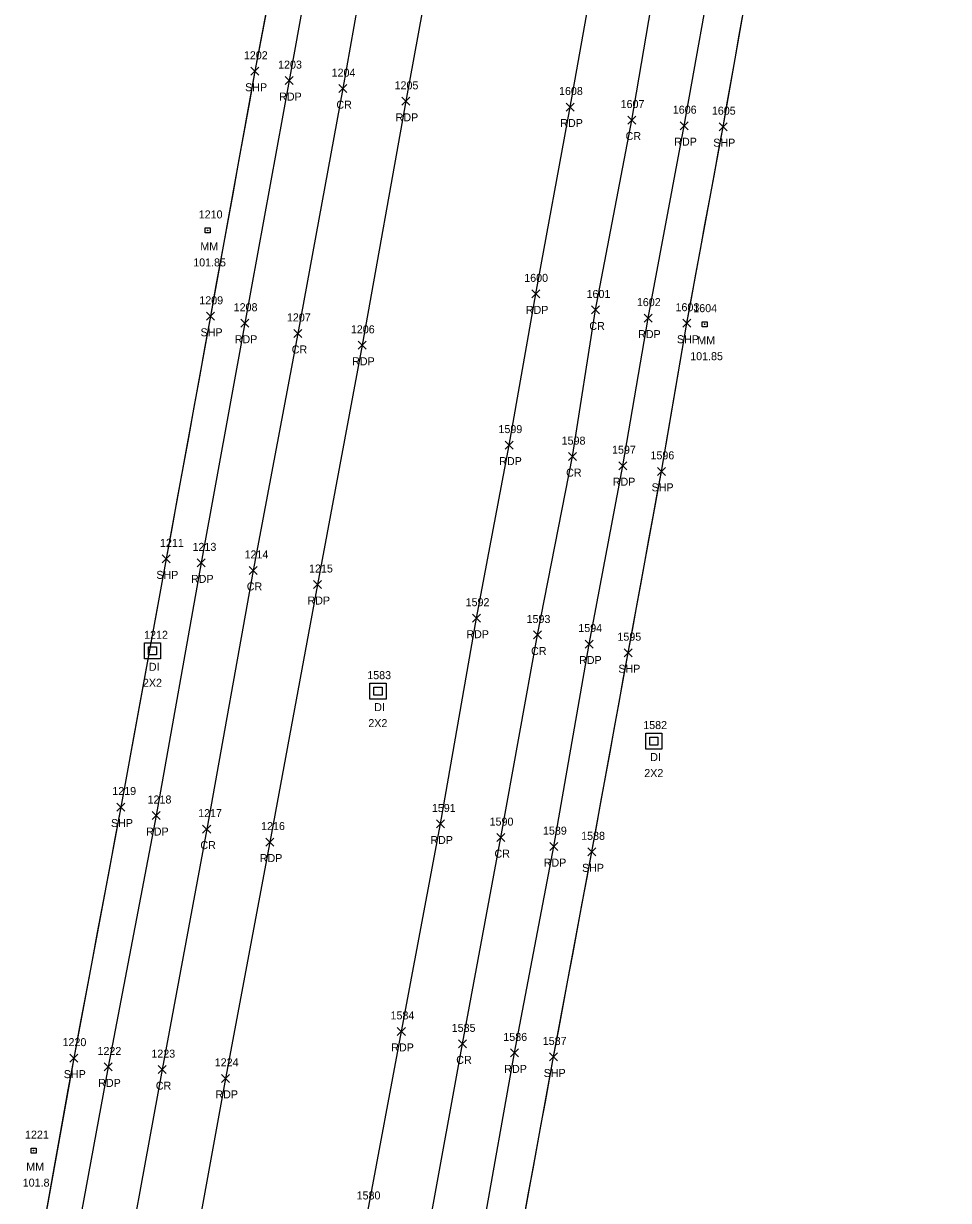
# Model space of a CAD drawing. Extents: x 1472022 to 1479249, y 777216 to 786527.
# Drawn here: x 1473773 to 1474004.1, y 780581.9 to 780876.1 of the extents above; entities that cross this region are included whole.
import ezdxf

# ---------------------------------------------------------------- set-up
doc = ezdxf.new("R2010")
doc.units = 0
for name, color, linetype in [('D_A', 7, 'Continuous'), ('D_C', 7, 'Continuous'), ('D_I', 7, 'Continuous'), ('DS', 7, 'Continuous'), ('LSOGP', 7, 'Continuous'), ('P_A', 7, 'Continuous'), ('P_I', 7, 'Continuous'), ('P_TIC', 7, 'Continuous'), ('PET', 7, 'Continuous'), ('PRC', 7, 'Continuous'), ('PSP', 7, 'Continuous'), ('S_A', 7, 'Continuous'), ('S_C', 7, 'Continuous'), ('S_I', 7, 'Continuous'), ('SRM', 7, 'Continuous')]:
    doc.layers.add(name, color=color, linetype=linetype)

msp = doc.modelspace()

# ---------------------------------------------------------------- linework, layer by layer
at = {"layer": 'DS'}
for p, q in [((1473803.21, 780721.26), (1473807.21, 780721.26)), ((1473803.21, 780717.26), (1473803.21, 780721.26)), ((1473807.21, 780721.26), (1473807.21, 780717.26)), ((1473804.21, 780718.26), (1473804.21, 780720.26)), ((1473804.21, 780720.26), (1473806.21, 780720.26)), ((1473806.21, 780718.26), (1473804.21, 780718.26)), ((1473805.22, 780719.27), (1473805.22, 780719.27)), ((1473805.22, 780719.27), (1473805.22, 780719.27)), ((1473806.21, 780720.26), (1473806.21, 780718.26)), ((1473807.21, 780717.26), (1473803.21, 780717.26)), ((1473859.53, 780711.19), (1473863.53, 780711.19)), ((1473859.53, 780707.19), (1473859.53, 780711.19)), ((1473860.53, 780708.19), (1473860.53, 780710.19)), ((1473860.53, 780710.19), (1473862.53, 780710.19)), ((1473862.53, 780710.19), (1473862.53, 780708.19)), ((1473863.53, 780711.19), (1473863.53, 780707.19)), ((1473863.53, 780707.19), (1473859.53, 780707.19)), ((1473862.53, 780708.19), (1473860.53, 780708.19)), ((1473861.54, 780709.19), (1473861.54, 780709.19)), ((1473861.54, 780709.19), (1473861.54, 780709.19)), ((1473928.48, 780698.71), (1473932.48, 780698.71)), ((1473928.48, 780694.71), (1473928.48, 780698.71)), ((1473929.48, 780695.71), (1473929.48, 780697.71)), ((1473929.48, 780697.71), (1473931.48, 780697.71)), ((1473931.48, 780697.71), (1473931.48, 780695.71)), ((1473932.48, 780698.71), (1473932.48, 780694.71)), ((1473932.48, 780694.71), (1473928.48, 780694.71)), ((1473931.48, 780695.71), (1473929.48, 780695.71)), ((1473930.49, 780696.71), (1473930.49, 780696.71)), ((1473930.49, 780696.71), (1473930.49, 780696.71))]:
    msp.add_line(p, q, dxfattribs=at)
at = {"layer": 'LSOGP'}
for points in [[(1473833.75, 780879.79), (1473832.27, 780871.97), (1473830.79, 780864.16), (1473829.4, 780856.5), (1473828.01, 780848.84), (1473826.62, 780841.19), (1473825.22, 780833.53), (1473823.83, 780825.87), (1473822.44, 780818.21), (1473821.05, 780810.56), (1473819.66, 780802.9), (1473818.28, 780795.32), (1473816.9, 780787.74), (1473815.52, 780780.16), (1473814.14, 780772.58), (1473812.76, 780765), (1473811.38, 780757.42), (1473810, 780749.84), (1473808.62, 780742.26), (1473807.2, 780734.51), (1473805.78, 780726.75), (1473804.36, 780718.99), (1473802.95, 780711.24), (1473801.53, 780703.48), (1473800.11, 780695.73), (1473798.69, 780687.97), (1473797.28, 780680.22), (1473795.8, 780672.37), (1473794.33, 780664.52), (1473792.86, 780656.68), (1473791.38, 780648.83), (1473789.91, 780640.99), (1473788.44, 780633.14), (1473786.96, 780625.29), (1473785.49, 780617.45), (1473784.06, 780609.5), (1473782.64, 780601.56), (1473781.22, 780593.62), (1473779.79, 780585.68), (1473778.37, 780577.73)], [(1473898.23, 780578.62), (1473899.25, 780584.21), (1473900.28, 780589.8), (1473901.3, 780595.38), (1473902.32, 780600.97), (1473903.35, 780606.56), (1473904.37, 780612.15), (1473905.39, 780617.74), (1473906.59, 780624.15), (1473907.79, 780630.56), (1473908.99, 780636.97), (1473910.18, 780643.38), (1473911.38, 780649.79), (1473912.58, 780656.2), (1473913.78, 780662.61), (1473914.98, 780669.02), (1473916.11, 780675.24), (1473917.24, 780681.46), (1473918.38, 780687.69), (1473919.51, 780693.91), (1473920.64, 780700.13), (1473921.78, 780706.36), (1473922.91, 780712.58), (1473924.04, 780718.8), (1473925.08, 780724.47), (1473926.12, 780730.14), (1473927.16, 780735.81), (1473928.2, 780741.47), (1473929.24, 780747.14), (1473930.28, 780752.81), (1473931.32, 780758.47), (1473932.36, 780764.14), (1473933.94, 780773.4), (1473935.52, 780782.65), (1473937.1, 780791.91), (1473938.69, 780801.17), (1473939.82, 780807.31), (1473940.96, 780813.45), (1473942.09, 780819.59), (1473943.23, 780825.74), (1473944.36, 780831.88), (1473945.5, 780838.02), (1473946.63, 780844.16), (1473947.77, 780850.3), (1473948.73, 780855.8), (1473949.7, 780861.3), (1473950.66, 780866.79), (1473951.63, 780872.29), (1473952.59, 780877.78)]]:
    msp.add_lwpolyline(points, dxfattribs=at)
at = {"layer": 'P_TIC'}
for points in [[(1473829.79, 780863.16), (1473831.79, 780865.16)], [(1473831.79, 780863.16), (1473829.79, 780865.16)], [(1473838.34, 780860.82), (1473840.34, 780862.82)], [(1473840.34, 780860.82), (1473838.34, 780862.82)], [(1473851.71, 780858.81), (1473853.71, 780860.81)], [(1473853.71, 780858.81), (1473851.71, 780860.81)], [(1473867.45, 780855.64), (1473869.45, 780857.64)], [(1473869.45, 780855.64), (1473867.45, 780857.64)], [(1473908.58, 780854.22), (1473910.58, 780856.22)], [(1473910.58, 780854.22), (1473908.58, 780856.22)], [(1473923.97, 780850.96), (1473925.97, 780852.96)], [(1473925.97, 780850.96), (1473923.97, 780852.96)], [(1473937.07, 780849.55), (1473939.07, 780851.55)], [(1473939.07, 780849.55), (1473937.07, 780851.55)], [(1473946.77, 780849.3), (1473948.77, 780851.3)], [(1473948.77, 780849.3), (1473946.77, 780851.3)], [(1473899.97, 780807.51), (1473901.97, 780809.51)], [(1473901.97, 780807.51), (1473899.97, 780809.51)], [(1473818.66, 780801.9), (1473820.66, 780803.9)], [(1473820.66, 780801.9), (1473818.66, 780803.9)], [(1473914.89, 780803.48), (1473916.89, 780805.48)], [(1473916.89, 780803.48), (1473914.89, 780805.48)], [(1473928.03, 780801.44), (1473930.03, 780803.44)], [(1473930.03, 780801.44), (1473928.03, 780803.44)], [(1473827.24, 780800.17), (1473829.24, 780802.17)], [(1473829.24, 780800.17), (1473827.24, 780802.17)], [(1473937.69, 780800.17), (1473939.69, 780802.17)], [(1473939.69, 780800.17), (1473937.69, 780802.17)], [(1473840.54, 780797.62), (1473842.54, 780799.62)], [(1473842.54, 780797.62), (1473840.54, 780799.62)], [(1473856.58, 780794.65), (1473858.58, 780796.65)], [(1473858.58, 780794.65), (1473856.58, 780796.65)], [(1473893.33, 780769.7), (1473895.33, 780771.7)], [(1473895.33, 780769.7), (1473893.33, 780771.7)], [(1473909.11, 780766.82), (1473911.11, 780768.82)], [(1473911.11, 780766.82), (1473909.11, 780768.82)], [(1473921.71, 780764.55), (1473923.71, 780766.55)], [(1473923.71, 780764.55), (1473921.71, 780766.55)], [(1473931.36, 780763.14), (1473933.36, 780765.14)], [(1473933.36, 780763.14), (1473931.36, 780765.14)], [(1473807.62, 780741.26), (1473809.62, 780743.26)], [(1473809.62, 780741.26), (1473807.62, 780743.26)], [(1473816.32, 780740.26), (1473818.32, 780742.26)], [(1473818.32, 780740.26), (1473816.32, 780742.26)], [(1473829.32, 780738.37), (1473831.32, 780740.37)], [(1473831.32, 780738.37), (1473829.32, 780740.37)], [(1473845.42, 780734.85), (1473847.42, 780736.85)], [(1473847.42, 780734.85), (1473845.42, 780736.85)], [(1473885.11, 780726.43), (1473887.11, 780728.43)], [(1473887.11, 780726.43), (1473885.11, 780728.43)], [(1473900.35, 780722.23), (1473902.35, 780724.23)], [(1473902.35, 780722.23), (1473900.35, 780724.23)], [(1473913.28, 780719.97), (1473915.28, 780721.97)], [(1473915.28, 780719.97), (1473913.28, 780721.97)], [(1473923.04, 780717.8), (1473925.04, 780719.8)], [(1473925.04, 780717.8), (1473923.04, 780719.8)], [(1473796.28, 780679.22), (1473798.28, 780681.22)], [(1473798.28, 780679.22), (1473796.28, 780681.22)], [(1473805.09, 780677.1), (1473807.09, 780679.1)], [(1473807.09, 780677.1), (1473805.09, 780679.1)], [(1473876.11, 780674.98), (1473878.11, 780676.98)], [(1473878.11, 780674.98), (1473876.11, 780676.98)], [(1473817.72, 780673.7), (1473819.72, 780675.7)], [(1473819.72, 780673.7), (1473817.72, 780675.7)], [(1473833.5, 780670.46), (1473835.5, 780672.46)], [(1473835.5, 780670.46), (1473833.5, 780672.46)], [(1473891.2, 780671.57), (1473893.2, 780673.57)], [(1473893.2, 780671.57), (1473891.2, 780673.57)], [(1473904.45, 780669.32), (1473906.45, 780671.32)], [(1473906.45, 780669.32), (1473904.45, 780671.32)], [(1473913.98, 780668.02), (1473915.98, 780670.02)], [(1473915.98, 780668.02), (1473913.98, 780670.02)], [(1473866.36, 780623.13), (1473868.36, 780625.13)], [(1473868.36, 780623.13), (1473866.36, 780625.13)], [(1473881.64, 780620.02), (1473883.64, 780622.02)], [(1473883.64, 780620.02), (1473881.64, 780622.02)], [(1473784.49, 780616.45), (1473786.49, 780618.45)], [(1473786.49, 780616.45), (1473784.49, 780618.45)], [(1473894.6, 780617.75), (1473896.6, 780619.75)], [(1473896.6, 780617.75), (1473894.6, 780619.75)], [(1473904.39, 780616.74), (1473906.39, 780618.74)], [(1473906.39, 780616.74), (1473904.39, 780618.74)], [(1473793.13, 780614.24), (1473795.13, 780616.24)], [(1473795.13, 780614.24), (1473793.13, 780616.24)], [(1473806.59, 780613.57), (1473808.59, 780615.57)], [(1473808.59, 780613.57), (1473806.59, 780615.57)], [(1473822.42, 780611.39), (1473824.42, 780613.39)], [(1473824.42, 780611.39), (1473822.42, 780613.39)]]:
    msp.add_lwpolyline(points, dxfattribs=at)
at = {"layer": 'PET'}
for points in [[(1473897.58, 781231.34), (1473890.82, 781171.41), (1473881.54, 781107.79), (1473871.75, 781046.99), (1473861.01, 780985.34), (1473850.75, 780924.87), (1473839.34, 780861.82), (1473828.24, 780801.17), (1473817.32, 780741.26), (1473806.09, 780678.1), (1473794.13, 780615.24), (1473782.52, 780552.37)], [(1473926.74, 781228.4), (1473920.04, 781167.79), (1473910.76, 781103.2), (1473901.27, 781040.55), (1473890.55, 780980.09), (1473879.69, 780918.18), (1473868.45, 780856.64), (1473857.58, 780795.65), (1473846.42, 780735.85), (1473834.5, 780671.46), (1473823.42, 780612.39), (1473811.33, 780545.89)], [(1473858.97, 780579.12), (1473867.36, 780624.13), (1473877.11, 780675.98), (1473886.11, 780727.43), (1473894.33, 780770.7), (1473900.97, 780808.51), (1473909.58, 780855.22), (1473917.72, 780901.01), (1473926.18, 780956.24), (1473935.05, 781009.43), (1473945.44, 781058.75), (1473953.71, 781110.88), (1473960.11, 781159.28), (1473966.39, 781210.69)], [(1473887.71, 780574.3), (1473895.6, 780618.75), (1473905.45, 780670.32), (1473914.28, 780720.97), (1473922.71, 780765.55), (1473929.03, 780802.44), (1473938.07, 780850.55), (1473946.09, 780895.57), (1473955.93, 780950.79), (1473964.68, 781004.2), (1473973.6, 781056.28), (1473981.03, 781105.64), (1473988.2, 781155.74), (1473994.49, 781207.67)]]:
    msp.add_lwpolyline(points, dxfattribs=at)
at = {"layer": 'PRC'}
for points in [[(1473910.61, 781230.26), (1473903.7, 781169.35), (1473894.45, 781104.8), (1473885.09, 781043.68), (1473874.53, 780983.16), (1473863.74, 780921.94), (1473852.71, 780859.81), (1473841.54, 780798.62), (1473830.32, 780739.37), (1473818.72, 780674.7), (1473807.59, 780614.57), (1473795.53, 780548.63)], [(1473874.56, 780576.61), (1473882.64, 780621.02), (1473892.2, 780672.57), (1473901.35, 780723.23), (1473910.11, 780767.82), (1473915.89, 780804.48), (1473924.97, 780851.96), (1473932.8, 780897.93), (1473943.22, 780952.96), (1473952.43, 781006.39), (1473960.52, 781056.72), (1473968.3, 781107.73), (1473975.01, 781157.69), (1473981.49, 781209.1)]]:
    msp.add_lwpolyline(points, dxfattribs=at)
at = {"layer": 'PSP'}
for points in [[(1473889.69, 781232.26), (1473882.53, 781172.78), (1473873.75, 781108.97), (1473864.09, 781048.42), (1473853.74, 780987.41), (1473842.61, 780926.67), (1473830.79, 780864.16), (1473819.66, 780802.9), (1473808.62, 780742.26), (1473797.28, 780680.22), (1473785.49, 780617.45), (1473774.09, 780553.9)], [(1473897.21, 780573.03), (1473905.39, 780617.74), (1473914.98, 780669.02), (1473924.04, 780718.8), (1473932.36, 780764.14), (1473938.69, 780801.17), (1473947.77, 780850.3), (1473955.49, 780894.27), (1473965.39, 780949.55), (1473974.6, 781002.86), (1473982.84, 781056.55), (1473990.34, 781104.33), (1473997.41, 781153.76), (1474004.06, 781207.93)]]:
    msp.add_lwpolyline(points, dxfattribs=at)
at = {"layer": 'SRM'}
for points in [[(1473818.32, 780825), (1473819.57, 780825), (1473819.57, 780823.75), (1473818.32, 780823.75)], [(1473942.51, 780801.55), (1473943.76, 780801.55), (1473943.76, 780800.3), (1473942.51, 780800.3)], [(1473774.83, 780594.95), (1473776.08, 780594.95), (1473776.08, 780593.7), (1473774.83, 780593.7)]]:
    msp.add_lwpolyline(points, close=True, dxfattribs=at)
for centre in [(1473818.95, 780824.37), (1473943.13, 780800.93), (1473775.46, 780594.32)]:
    msp.add_circle(centre, 0.0833, dxfattribs=at)

# ---------------------------------------------------------------- texts
at = {"layer": 'D_A'}
for p in [(1473804.27, 780714.27), (1473860.59, 780704.19), (1473929.54, 780691.71)]:
    msp.add_text('DI', height=2, dxfattribs=at).set_placement(p)
at = {"layer": 'D_C'}
for p in [(1473802.79, 780710.27), (1473859.11, 780700.19), (1473928.06, 780687.71)]:
    msp.add_text('2X2', height=2, dxfattribs=at).set_placement(p)
at = {"layer": 'D_I'}
for s, p in [('1212', (1473803.09, 780722.27)), ('1583', (1473858.84, 780712.19)), ('1582', (1473927.8, 780699.71))]:
    msp.add_text(s, height=2, dxfattribs=at).set_placement(p)
at = {"layer": 'P_A'}
for s, p in [('SHP', (1473828.33, 780859.16)), ('RDP', (1473836.83, 780856.82)), ('CR', (1473851.14, 780854.81)), ('RDP', (1473865.93, 780851.64)), ('RDP', (1473907.07, 780850.22)), ('CR', (1473923.4, 780846.96)), ('RDP', (1473935.55, 780845.55)), ('SHP', (1473945.3, 780845.3)), ('RDP', (1473898.46, 780803.51)), ('CR', (1473914.33, 780799.48)), ('SHP', (1473817.19, 780797.9)), ('RDP', (1473825.73, 780796.17)), ('RDP', (1473926.52, 780797.44)), ('SHP', (1473936.22, 780796.17)), ('CR', (1473839.98, 780793.62)), ('RDP', (1473855.07, 780790.65)), ('RDP', (1473891.82, 780765.7)), ('CR', (1473908.54, 780762.82)), ('RDP', (1473920.19, 780760.55)), ('SHP', (1473929.89, 780759.14)), ('SHP', (1473806.15, 780737.26)), ('RDP', (1473814.8, 780736.26)), ('CR', (1473828.75, 780734.37)), ('RDP', (1473843.91, 780730.85)), ('RDP', (1473883.6, 780722.43)), ('CR', (1473899.78, 780718.23)), ('RDP', (1473911.77, 780715.97)), ('SHP', (1473921.58, 780713.8)), ('SHP', (1473794.81, 780675.22)), ('RDP', (1473803.58, 780673.1)), ('CR', (1473817.15, 780669.7)), ('RDP', (1473874.6, 780670.98)), ('RDP', (1473831.99, 780666.46)), ('CR', (1473890.64, 780667.57)), ('RDP', (1473902.94, 780665.32)), ('SHP', (1473912.51, 780664.02)), ('RDP', (1473864.84, 780619.13)), ('CR', (1473881.08, 780616.02)), ('RDP', (1473893.08, 780613.75)), ('SHP', (1473783.02, 780612.45)), ('RDP', (1473791.62, 780610.24)), ('SHP', (1473902.93, 780612.74)), ('CR', (1473806.02, 780609.57)), ('RDP', (1473820.91, 780607.39))]:
    msp.add_text(s, height=2, dxfattribs=at).set_placement(p)
at = {"layer": 'P_I'}
for s, p in [('1202', (1473828.02, 780867.16)), ('1203', (1473836.57, 780864.82)), ('1204', (1473849.94, 780862.81)), ('1205', (1473865.67, 780859.64)), ('1608', (1473906.76, 780858.22)), ('1607', (1473922.15, 780854.96)), ('1606', (1473935.19, 780853.55)), ('1605', (1473944.95, 780853.3)), ('1600', (1473898.07, 780811.51)), ('1601', (1473913.64, 780807.48)), ('1209', (1473816.88, 780805.9)), ('1602', (1473926.21, 780805.44)), ('1208', (1473825.47, 780804.17)), ('1207', (1473838.77, 780801.62)), ('1603', (1473935.87, 780804.17)), ('1206', (1473854.75, 780798.65)), ('1599', (1473891.63, 780773.7)), ('1598', (1473907.42, 780770.82)), ('1597', (1473920.01, 780768.55)), ('1596', (1473929.61, 780767.14)), ('1211', (1473807.06, 780745.26)), ('1213', (1473815.19, 780744.26)), ('1214', (1473828.19, 780742.37)), ('1215', (1473844.3, 780738.85)), ('1592', (1473883.42, 780730.43)), ('1593', (1473898.65, 780726.23)), ('1594', (1473911.58, 780723.97)), ('1595', (1473921.35, 780721.8)), ('1219', (1473795.14, 780683.22)), ('1218', (1473803.96, 780681.1)), ('1591', (1473874.99, 780678.98)), ('1217', (1473816.59, 780677.7)), ('1590', (1473889.42, 780675.57)), ('1216', (1473832.32, 780674.46)), ('1589', (1473902.75, 780673.32)), ('1588', (1473912.29, 780672.02)), ('1584', (1473864.66, 780627.13)), ('1585', (1473879.95, 780624.02)), ('1220', (1473782.71, 780620.45)), ('1586', (1473892.85, 780621.75)), ('1587', (1473902.7, 780620.74)), ('1222', (1473791.44, 780618.24)), ('1223', (1473804.9, 780617.57)), ('1224', (1473820.73, 780615.39)), ('1580', (1473856.19, 780582.12))]:
    msp.add_text(s, height=2, dxfattribs=at).set_placement(p)
at = {"layer": 'S_A'}
for p in [(1473817.14, 780819.37), (1473941.32, 780795.93), (1473773.64, 780589.32)]:
    msp.add_text('MM', height=2, dxfattribs=at).set_placement(p)
at = {"layer": 'S_C'}
for s, p in [('101.85', (1473815.36, 780815.37)), ('101.85', (1473939.54, 780791.93)), ('101.8', (1473772.76, 780585.32))]:
    msp.add_text(s, height=2, dxfattribs=at).set_placement(p)
at = {"layer": 'S_I'}
for s, p in [('1210', (1473816.74, 780827.37)), ('1604', (1473940.31, 780803.93)), ('1221', (1473773.33, 780597.32))]:
    msp.add_text(s, height=2, dxfattribs=at).set_placement(p)

doc.saveas('drawing.dxf')
